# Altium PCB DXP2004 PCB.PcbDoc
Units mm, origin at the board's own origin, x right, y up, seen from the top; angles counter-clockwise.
Board outline 152.4 x 101.6 mm, 2 copper layers (Top Layer, Bottom Layer); 37 components, 0 nets, 178 pads, 0 vias.
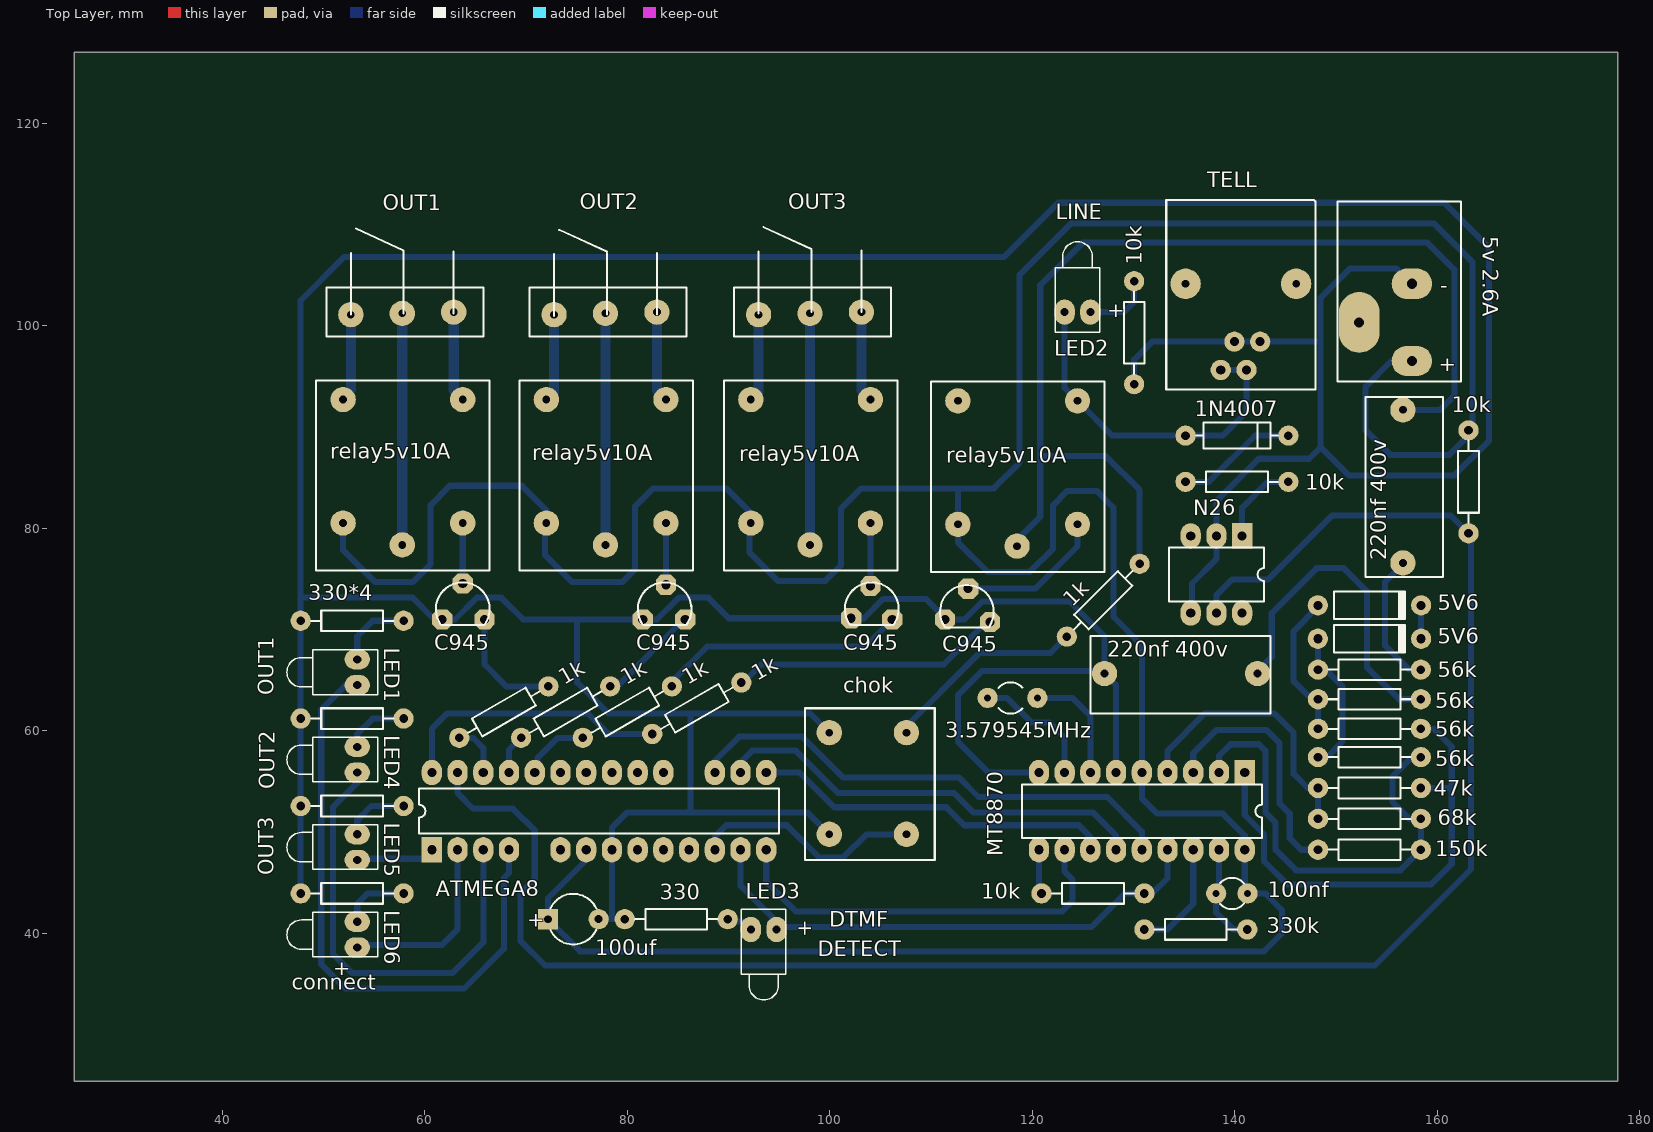
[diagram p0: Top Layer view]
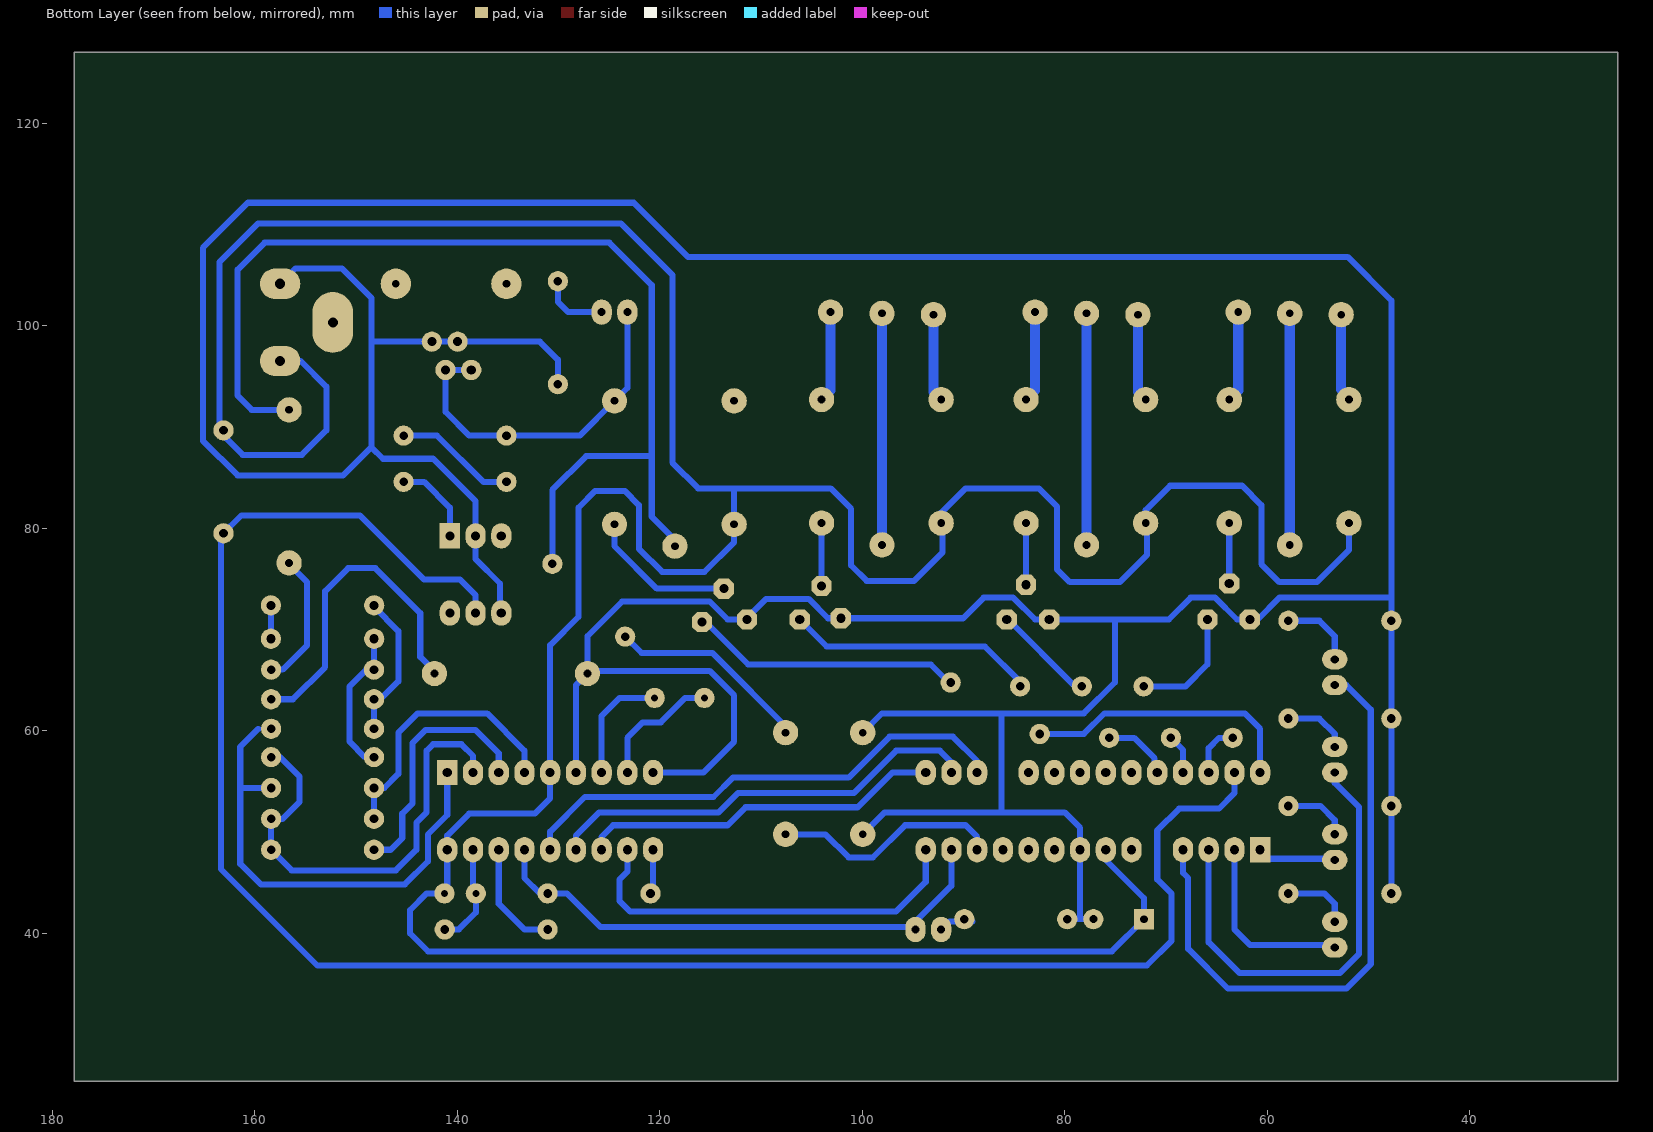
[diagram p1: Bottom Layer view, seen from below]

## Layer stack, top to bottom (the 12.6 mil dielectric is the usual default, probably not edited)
Top Layer: signal copper 0.0356
Dielectric: dielectric 0.32, FR-4, Dk 4.8
Bottom Layer: signal copper 0.0356

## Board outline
25.4,25.4 177.8,25.4 177.8,127 25.4,127

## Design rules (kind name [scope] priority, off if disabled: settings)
Clearance [All] p1: gap=0.254
ComponentClearance [All] p1: gap=0.254 collisioncheckmode=0
PolygonConnect [All] p1: connectstyle=Relief reliefconductorwidth=0.254 reliefentries=4 polygonreliefangle="90 Angle"
RoutingLayers [All] p1: top layer=Horizontal bottom layer=Vertical
RoutingVias [All] p1: holewidth=0.711 width=1.27 viastyle="Through Hole" minholewidth=0.711 minwidth=1.27 maxholewidth=0.711 maxwidth=1.27
SolderMaskExpansion [All] p1: expansion=0.102
TestPointUsage [All] p1: valid=0 allowmultiple=FALSE
Testpoint [All] p1: side=15 testpointundercomponent=TRUE minsize=1.016 maxsize=2.54 preferedsize=1.524 minholesize=0 maxholesize=1.016 preferedholesize=0.813 testpointgrid=0.025 style=1023 order=1234567890
Width [All] p1: maxlimit=0.254 minlimit=0.254 preferedwidth=0.254
16 further rules are at their usual default settings.

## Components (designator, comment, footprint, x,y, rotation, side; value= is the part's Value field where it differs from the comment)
1k "Comment" AXIAL-0.4 127,72.898 r45 top
1k "Comment" AXIAL-0.4 67.818,61.849 r30 top
1k "Comment" AXIAL-0.4 73.914,61.849 r30 top
1k "Comment" AXIAL-0.4 80.01,61.849 r30 top
1k "Comment" AXIAL-0.4 86.868,62.23 r30 top
1N4007 "Comment" DIODE-0.4 140.208,89.154 r0 top
3.579545MHz "Comment" BCY-W2/D3.1#1 117.856,63.246 r270 top
5V6 "Comment" DIO10.2-7X2.7 153.289,72.39 r0 top
5V6 "Comment" DIO10.2-7X2.7 153.289,69.088 r0 top
10k "Comment" AXIAL-0.4 163.068,84.582 r270 top
10k "Comment" AXIAL-0.4 125.984,43.942 r180 top
10k "Comment" AXIAL-0.4 130.048,99.314 r270 top
10k "Comment" AXIAL-0.4 140.208,84.582 r180 top
47k "Comment" AXIAL-0.4 153.289,54.356 r180 top
56k "Comment" AXIAL-0.4 153.289,57.404 r180 top
56k "Comment" AXIAL-0.4 153.289,60.198 r180 top
56k "Comment" AXIAL-0.4 153.289,63.119 r180 top
56k "Comment" AXIAL-0.4 153.289,66.04 r180 top
68k "Comment" AXIAL-0.4 153.289,51.308 r180 top
100nf "Comment" BCY-W2/D3.1#2 139.7,43.942 r90 top
100uf "Comment" CAPPR5-5X5 74.676,41.402 r0 top
150k "Comment" AXIAL-0.4 153.289,48.26 r180 top
330 "Comment" AXIAL-0.4 84.836,41.402 r0 top
330*4 "Comment" AXIAL-0.4 52.832,70.866 r180 top
330k "Comment" AXIAL-0.4 136.144,40.386 r180 top
ATMEGA8 "Comment" 28P3 77.216,52.07 r0 top
LED1 "Comment" LED-1 53.34,65.786 r180 top
LED2 "Comment" LED-1 124.46,101.346 r90 top
LED3 "Comment" LED-1 93.472,40.386 r270 top
LED4 "Comment" LED-1 53.34,57.15 r180 top
LED5 "Comment" LED-1 53.34,48.514 r180 top
LED6 "Comment" LED-1 53.34,39.878 r180 top
MT8870 "Comment" DIP-18 130.81,52.07 r180 top
N26 "Comment" DIP-6 138.176,75.438 r180 top
? "Comment" AXIAL-0.4 52.832,43.942 r180 top
? "Comment" AXIAL-0.4 52.832,52.578 r180 top
? "Comment" AXIAL-0.4 52.832,61.214 r180 top

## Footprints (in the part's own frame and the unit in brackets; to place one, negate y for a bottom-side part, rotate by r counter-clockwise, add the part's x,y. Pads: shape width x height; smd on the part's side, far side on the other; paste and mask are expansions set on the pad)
28P3 [mm] "DIP; 28 Leads; Row Spacing 7.62 mm; Pitch 2.54 mm"
  rect 2x2.5 hole 0.9: 1(-16.51,-3.81)
  oval 2x2.5 hole 0.9: 2(-13.97,-3.81) 3(-11.43,-3.81) 4(-8.89,-3.81) 6(-3.81,-3.81) 7(-1.27,-3.81) 8(1.27,-3.81) 9(3.81,-3.81) 10(6.35,-3.81) 11(8.89,-3.81) 12(11.43,-3.81) 13(13.97,-3.81) 14(16.51,-3.81) 15(16.51,3.81) 16(13.97,3.81) 17(11.43,3.81) 19(6.35,3.81) 20(3.81,3.81) 21(1.27,3.81) 22(-1.27,3.81) 23(-3.81,3.81) 24(-6.35,3.81) 25(-8.89,3.81) 26(-11.43,3.81) 27(-13.97,3.81) 28(-16.51,3.81)
  round 0 all layers, no hole: 5(-6.35,-3.81) 18(8.89,3.81)
  silkscreen extent -17.78,-2.23 17.78,2.23
AXIAL-0.4 [mm]
  round 2 hole 0.85: 1(-5.08,0) 2(5.08,0)
  silkscreen extent -4.06,-1.02 4.06,1.02
BCY-W2/D3.1#1 [mm]
  round 2 hole 0.7: 1(0,2.636) 2(0,-2.272)
  silkscreen extent -1.55,-1.19 1.55,1.17
BCY-W2/D3.1#2 [mm]
  round 2 hole 0.7: 1(0,1.55) 2(0,-1.55)
  silkscreen extent -1.55,-1.19 1.55,1.17
CAPPR5-5X5 [mm]
  rect 2x2 hole 0.75: 1(-2.5,0)
  round 2 hole 0.8: 2(2.5,0)
  silkscreen extent -2.26,-2.5 2.27,2.5
DIO10.2-7X2.7 [mm]
  round 2 hole 0.9: 1(-5.1,0) 2(5.1,0)
  silkscreen extent -3.5,-1.35 3.6,1.35
DIODE-0.4 [mm]
  round 2 hole 0.85: 1(-5.08,0) 2(5.08,0)
  silkscreen extent -4.06,-1.27 4.06,1.27
DIP-6 [mm]
  rect 2x2.5 hole 0.9: 1(-2.54,-3.81)
  oval 2x2.5 hole 0.9: 2(0,-3.81) 3(2.54,-3.81) 4(2.54,3.81) 5(0,3.81) 6(-2.54,3.81)
  silkscreen extent -4.7,-2.65 4.7,2.65
DIP-18 [mm]
  rect 2x2.5 hole 0.9: 1(-10.16,-3.81)
  oval 2x2.5 hole 0.9: 2(-7.62,-3.81) 3(-5.08,-3.81) 4(-2.54,-3.81) 5(0,-3.81) 6(2.54,-3.81) 7(5.08,-3.81) 8(7.62,-3.81) 9(10.16,-3.81) 10(10.16,3.81) 11(7.62,3.81) 12(5.08,3.81) 13(2.54,3.81) 14(0,3.81) 15(-2.54,3.81) 16(-5.08,3.81) 17(-7.62,3.81) 18(-10.16,3.81)
  silkscreen extent -11.85,-2.65 11.85,2.65
LED-1 [mm]
  oval 2.5x2 hole 0.8: 1(0,1.27) 2(0,-1.27)
  silkscreen extent -2,-2.2 6.95,2.2

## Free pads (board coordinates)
  round 2.5 hole 0.762: 0(51.943,80.518) 0(51.943,92.71) 0(52.705,101.092) 0(57.785,78.359) 0(57.785,101.219) 0(62.865,101.346) 0(72.009,80.518) 0(72.009,92.71) 0(72.771,101.092) 0(77.851,78.359) 0(77.851,101.219) 0(82.931,101.346) 0(92.202,80.518) 0(92.202,92.71) 0(92.964,101.092) 0(98.044,78.359) 0(98.044,101.219) 0(103.124,101.346) 0(112.649,80.391) 0(112.649,92.583) 0(118.491,78.232) 1(63.754,80.518) 1(63.754,92.71) 1(83.82,80.518) 1(83.82,92.71) 1(104.013,80.518) 1(104.013,92.71) 1(124.46,80.391) 1(124.46,92.583) 4(99.949,49.784) 4(99.949,59.817) 5(107.569,49.784) 5(107.569,59.817) 6(127.127,65.659) 6(156.591,76.581) 7(142.24,65.659) 7(156.591,91.694)
  oval 4x3 hole 1: 0(157.48,96.52) 1(157.48,104.14)
  oct 2x2 hole 0.9: 1(61.722,70.993) 1(81.534,70.993) 1(102.108,71.12) 1(111.379,70.993) 2(63.754,74.549) 2(83.82,74.422) 2(104.013,74.295) 2(113.665,74.041) 3(65.913,70.993) 3(85.725,70.993) 3(106.172,70.993) 3(115.824,70.739)
  round 2 hole 0.9: 1(138.606,95.631) 1(139.954,98.428) 2(141.146,95.631) 2(142.494,98.428)
  round 3 hole 0.762: 2(135.13,104.14) 3(146.05,104.14)
  oval 4x6 hole 1: 2(152.273,100.33)

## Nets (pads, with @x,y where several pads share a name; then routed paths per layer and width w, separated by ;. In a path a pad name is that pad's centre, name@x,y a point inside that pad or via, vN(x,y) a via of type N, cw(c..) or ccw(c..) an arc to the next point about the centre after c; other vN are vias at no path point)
pads on no net: 1k.1 1k.2 1N4007.1 1N4007.2 3.579545MHz.1 3.579545MHz.2 5V6.1 5V6.2 10k.1 10k.2 47k.1 47k.2 56k.1 56k.2 68k.1 68k.2 100nf.1 100nf.2 100uf.1 100uf.2 150k.1 150k.2 330*4.1 330*4.2 330.1 330.2 330k.1 330k.2 ?.1 ?.2 ATMEGA8.1 ATMEGA8.2 ATMEGA8.3 ATMEGA8.4 ATMEGA8.5 ATMEGA8.6 ATMEGA8.7 ATMEGA8.8 ATMEGA8.9 ATMEGA8.10 ATMEGA8.11 ATMEGA8.12 ATMEGA8.13 ATMEGA8.14 ATMEGA8.15 ATMEGA8.16 ATMEGA8.17 ATMEGA8.18 ATMEGA8.19 ATMEGA8.20 ATMEGA8.21 ATMEGA8.22 ATMEGA8.23 ATMEGA8.24 ATMEGA8.25 ATMEGA8.26 ATMEGA8.27 ATMEGA8.28 LED1.1 LED1.2 LED2.1 LED2.2 LED3.1 LED3.2 LED4.1 LED4.2 LED5.1 LED5.2 LED6.1 LED6.2 MT8870.1 MT8870.2 MT8870.3 MT8870.4 MT8870.5 MT8870.6 MT8870.7 MT8870.8 MT8870.9 MT8870.10 MT8870.11 MT8870.12 MT8870.13 MT8870.14 MT8870.15 MT8870.16 MT8870.17 MT8870.18 N26.1 N26.2 N26.3 N26.4 N26.5 N26.6
copper on no net: | length 2220.7
  Top Layer w1: 156.591,97.409 158.115,97.409 158.877,96.647 ; 156.718,95.758 157.48,96.52 ; 157.226,104.14 157.48,104.14
  Bottom Layer w0.6: 47.752,44.069 47.752,79.248 ; 47.752,73.279 47.879,73.152 58.801,73.152 60.96,70.993 61.722,70.993 62.992,70.993 65.151,73.152 67.564,73.152 69.723,70.993 81.534,70.993 82.931,70.993 85.09,73.152 88.011,73.152 90.043,71.12 102.108,71.12 103.378,71.12 105.283,73.025 109.474,73.025 111.379,71.12 111.379,70.993 113.284,70.993 115.062,72.771 117.602,72.771 123.698,72.771 127.127,69.342 127.127,65.659 128.27,64.516 128.27,58.166 ; 47.752,78.486 47.752,102.489 52.07,106.807 117.221,106.807 122.555,112.141 160.655,112.141 165.1,107.696 165.1,88.646 161.671,85.217 151.257,85.217 148.463,88.011 ; 51.943,80.518 51.943,77.851 55.118,74.676 58.801,74.676 60.579,76.454 60.579,82.296 62.484,84.201 69.596,84.201 72.009,81.788 72.009,80.518 71.882,80.391 71.882,77.343 74.549,74.676 79.502,74.676 80.772,75.946 80.772,82.169 82.55,83.947 89.789,83.947 92.202,81.534 92.202,80.518 92.075,80.391 92.075,77.597 94.869,74.803 99.568,74.803 101.092,76.327 101.092,81.915 103.124,83.947 110.744,83.947 ; 53.213,38.862 61.722,38.862 63.246,40.386 63.246,48.26 ; 53.213,47.371 59.817,47.371 60.706,48.26 ; 53.34,41.148 53.34,42.926 54.356,43.942 57.912,43.942 ; 53.34,49.784 53.34,51.181 54.737,52.578 57.912,52.578 ; 53.34,55.88 53.34,54.864 50.927,52.451 50.927,37.973 52.832,36.068 62.738,36.068 65.786,39.116 65.786,48.26 ; 53.34,58.42 53.34,59.69 54.864,61.214 57.912,61.214 ; 53.34,64.516 52.197,64.516 49.784,62.103 49.784,36.957 52.197,34.544 63.881,34.544 67.818,38.481 67.818,45.466 68.326,45.974 68.326,48.26 ; 53.34,67.056 53.34,69.342 54.864,70.866 57.912,70.866 ; 60.706,55.88 60.706,60.198 62.23,61.722 76.073,61.722 78.105,59.69 82.469,59.69 ; 63.246,55.88 63.246,53.848 64.77,52.324 68.707,52.324 70.866,50.165 70.866,45.339 69.469,43.942 69.469,39.243 71.882,36.83 73.152,36.83 153.797,36.83 163.322,46.355 163.322,76.073 ; 63.419,59.309 64.77,59.309 65.786,58.293 65.786,55.88 ; 63.754,73.914 63.754,80.518 ; 65.913,70.993 65.913,66.548 68.072,64.389 72.217,64.389 ; 68.326,55.88 68.326,58.12 69.515,59.309 ; 71.12,55.88 71.12,57.277 73.152,59.309 75.611,59.309 ; 75.057,70.993 75.057,64.77 78.105,61.722 83.566,61.722 ; 75.946,48.26 75.946,47.244 72.176,43.474 72.176,41.402 75.351,38.227 82.931,38.227 ; 77.176,41.402 79.502,41.402 79.756,41.148 ; 78.486,41.402 78.486,46.228 ; 78.486,45.732 78.486,48.26 78.486,50.419 80.01,51.943 84.328,51.943 97.79,51.943 99.949,49.784 ; 78.486,64.516 79.121,64.516 85.598,70.993 85.725,70.993 ; 82.677,38.227 142.875,38.227 144.653,40.005 144.653,42.291 143.002,43.942 141.25,43.942 140.97,44.222 140.97,48.26 ; 83.185,61.722 91.821,61.722 98.044,61.722 99.949,59.817 ; 83.693,73.914 83.82,74.041 83.82,80.518 ; 84.409,64.389 84.409,64.851 87.884,68.326 103.505,68.326 106.172,70.993 ; 86.233,51.943 86.233,61.722 ; 88.646,48.26 88.646,49.53 89.789,50.673 95.758,50.673 98.933,47.498 101.346,47.498 103.632,49.784 107.569,49.784 ; 88.646,56.134 88.646,57.023 91.059,59.436 97.282,59.436 101.346,55.372 112.776,55.372 114.681,53.467 127.381,53.467 130.81,50.038 130.81,48.26 ; 89.102,41.189 91.399,41.189 92.202,40.386 ; 91.186,48.26 91.186,44.704 95.25,40.64 125.857,40.64 129.159,43.942 131.572,43.942 131.826,43.942 133.35,45.466 133.35,48.26 ; 91.186,55.88 91.186,56.896 92.329,58.039 96.647,58.039 100.838,53.848 112.268,53.848 114.173,51.943 125.984,51.943 128.27,49.657 128.27,48.26 ; 91.267,64.77 91.44,64.77 93.218,66.548 111.252,66.548 115.697,70.993 ; 93.726,48.26 93.726,45.085 96.647,42.164 122.936,42.164 123.952,43.18 123.952,45.339 123.19,46.101 123.19,48.26 ; 93.726,55.88 97.028,55.88 100.457,52.451 111.506,52.451 113.284,50.673 124.587,50.673 125.73,49.53 125.73,48.26 ; 104.013,80.518 104.013,74.041 104.14,73.914 ; 107.569,59.817 106.934,59.817 114.808,67.691 121.793,67.691 123.408,69.306 ; 110.109,83.947 116.205,83.947 118.745,86.487 118.745,105.029 123.825,110.109 159.639,110.109 163.449,106.299 163.449,89.535 161.163,87.249 155.321,87.249 152.908,89.662 152.908,93.98 155.448,96.52 157.48,96.52 ; 112.649,83.82 112.649,80.391 112.649,78.613 115.57,75.692 119.761,75.692 122.047,77.978 122.047,82.296 123.444,83.693 126.365,83.693 128.016,82.042 128.016,71.247 130.81,68.453 130.81,57.531 ; 113.538,74.041 120.269,74.041 124.46,78.232 124.46,80.391 ; 115.584,63.246 117.475,63.246 119.888,60.833 121.666,60.833 123.19,59.309 123.19,55.88 ; 118.618,78.232 118.491,78.232 118.491,78.867 120.777,81.153 120.777,104.013 124.968,108.204 159.004,108.204 161.671,105.537 161.671,93.091 160.274,91.694 156.591,91.694 ; 120.492,63.246 123.952,63.246 125.73,61.468 125.73,55.88 ; 120.65,48.26 120.65,44.704 121.412,43.942 ; 120.65,55.88 115.697,55.88 112.649,58.928 112.649,63.5 115.062,65.913 127,65.913 127.127,66.04 ; 120.777,87.122 127.254,87.122 130.592,83.784 130.592,76.49 ; 123.19,100.076 123.19,101.346 123.19,93.853 124.46,92.583 127.889,89.154 135.128,89.154 138.811,89.154 141.146,91.489 141.146,95.631 138.606,95.631 138.557,95.631 ; 125.73,101.346 129.032,101.346 130.048,102.362 130.048,104.394 ; 128.27,55.88 128.27,58.801 ; 130.048,94.234 130.048,96.647 131.829,98.428 139.954,98.428 142.494,98.428 148.463,98.425 ; 130.81,55.626 130.81,58.166 ; 130.81,55.88 130.81,53.34 132.334,51.816 138.811,51.816 140.97,49.657 140.97,48.26 ; 131.064,40.386 133.35,40.386 135.89,42.926 135.89,48.26 ; 133.35,55.88 133.35,58.039 137.033,61.722 143.891,61.722 145.796,59.817 145.796,55.753 147.193,54.356 148.209,54.356 148.209,51.054 ; 135.128,84.582 137.414,84.582 141.986,89.154 145.288,89.154 ; 135.763,71.882 135.763,74.549 138.176,76.962 138.176,79.248 138.176,82.677 142.367,86.868 147.32,86.868 148.463,88.011 ; 135.89,55.88 135.89,57.785 138.176,60.071 143.129,60.071 144.399,58.801 144.399,52.832 145.415,51.816 145.415,49.403 146.558,48.26 148.209,48.26 ; 138.176,71.628 138.176,73.406 139.7,74.93 143.256,74.93 149.606,81.28 161.29,81.28 163.322,79.248 163.322,75.819 ; 138.43,48.26 138.43,44.222 138.15,43.942 138.15,42.063 139.827,40.386 141.224,40.386 ; 138.43,55.88 138.43,57.531 139.573,58.674 142.367,58.674 143.002,58.039 143.002,51.943 144.018,50.927 144.018,48.26 146.05,46.228 156.337,46.228 158.369,48.26 158.369,51.308 157.226,51.308 155.575,52.959 155.575,55.499 157.48,57.404 158.369,57.404 ; 140.716,79.248 140.716,82.042 143.256,84.582 145.288,84.582 ; 140.97,45.212 140.97,48.26 ; 140.97,55.88 140.97,51.689 142.875,49.784 142.875,47.117 145.161,44.831 159.385,44.831 161.417,46.863 161.417,58.42 159.639,60.198 ; 142.24,65.659 142.24,65.913 143.637,67.31 143.637,71.628 148.082,76.073 150.749,76.073 153.035,73.787 153.035,66.294 156.21,63.119 158.369,63.119 ; 148.189,69.088 148.189,66.06 148.209,66.04 148.971,66.04 150.622,64.389 150.622,58.928 149.098,57.404 148.209,57.404 ; 148.189,72.39 148.189,72.243 145.796,69.85 145.796,64.897 147.574,63.119 148.209,63.119 148.209,60.198 ; 156.591,76.581 156.591,76.454 154.813,74.676 154.813,68.453 157.226,66.04 158.369,66.04 ; 157.48,104.14 155.956,105.664 151.384,105.664 148.463,102.743 148.463,88.011 ; 158.369,54.356 161.29,54.356 ; 158.389,69.088 158.389,72.39
  Bottom Layer w1: 51.689,92.71 52.705,93.726 52.705,101.092 ; 57.785,78.359 57.785,101.219 ; 62.865,101.346 62.865,93.599 63.754,92.71 ; 72.009,92.71 72.771,93.472 72.771,101.092 ; 77.851,78.359 77.851,101.219 ; 82.931,101.346 82.931,93.599 83.82,92.71 ; 92.202,92.71 92.964,93.472 92.964,101.092 ; 98.044,101.219 98.044,78.613 98.171,78.486 ; 103.124,101.346 103.124,93.599 104.013,92.71 ; 118.491,78.486 118.618,78.359

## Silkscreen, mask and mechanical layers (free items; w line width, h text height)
Top Overlay:
  lines w0.2: 52.705,101.092 52.705,107.188 ; 53.213,109.601 57.912,107.442 ; 57.912,101.219 57.912,107.315 ; 61.583,70.489 cw(c63.754,72.009) 65.925,70.489 ; 61.654,70.459 65.854,70.459 ; 62.865,101.219 62.865,107.315 ; 72.771,100.965 72.771,107.061 ; 73.279,109.474 77.978,107.315 ; 77.978,101.092 77.978,107.188 ; 81.522,70.489 cw(c83.693,72.009) 85.864,70.489 ; 81.593,70.459 85.793,70.459 ; 82.931,101.092 82.931,107.188 ; 92.964,101.219 92.964,107.315 ; 93.472,109.728 98.171,107.569 ; 98.171,101.346 98.171,107.442 ; 101.969,70.489 cw(c104.14,72.009) 106.311,70.489 ; 102.04,70.459 106.24,70.459 ; 103.124,101.346 103.124,107.442 ; 111.367,70.235 cw(c113.538,71.755) 115.709,70.235 ; 111.438,70.205 115.638,70.205 ; 133.223,112.395 133.223,93.726 147.955,93.726 147.955,112.266 147.957,112.268 147.83,112.395 133.225,112.395 ; 49.276,75.819 49.276,94.615 49.657,94.615 66.421,94.615 66.421,75.819 49.276,75.819 ; 50.292,98.933 50.292,103.759 65.786,103.759 65.786,98.933 50.292,98.933 ; 69.342,75.819 69.342,94.615 69.723,94.615 86.487,94.615 86.487,75.819 69.342,75.819 ; 70.358,98.933 70.358,103.759 85.852,103.759 85.852,98.933 70.358,98.933 ; 89.535,75.819 89.535,94.615 89.916,94.615 106.68,94.615 106.68,75.819 89.535,75.819 ; 90.551,98.933 90.551,103.759 106.045,103.759 106.045,98.933 90.551,98.933 ; 97.536,47.244 97.536,62.23 110.363,62.23 110.363,47.244 97.536,47.244 ; 109.982,75.692 109.982,94.488 110.363,94.488 127.127,94.488 127.127,75.692 109.982,75.692 ; 125.73,61.722 143.51,61.722 143.51,69.342 125.73,69.342 125.73,61.722 ; 150.114,94.488 162.306,94.488 162.306,97.028 162.306,112.268 150.114,112.268 150.114,94.488 ; 152.908,75.184 152.908,92.964 160.528,92.964 160.528,75.184 152.908,75.184
  text "TELL" at 137.287,113.665 h1.52
  text "OUT2" at 75.311,111.506 h1.52
  text "OUT3" at 95.885,111.506 h1.52
  text "OUT1" at 55.88,111.379 h1.52
  text "LINE" at 122.301,110.49 h1.52
  text "5v 2.6A" at 164.465,108.839 h1.52 r270
  text "-" at 160.274,103.251 h1.52
  text "+" at 127.381,100.838 h1.52
  text "+" at 160.147,95.504 h1.52
  text "relay5v10A" at 50.673,86.868 h1.52
  text "relay5v10A" at 70.612,86.741 h1.52
  text "relay5v10A" at 91.059,86.614 h1.52
  text "relay5v10A" at 111.506,86.487 h1.52
  text "220nf 400v" at 154.94,76.835 h1.52 r90
  text "C945" at 60.96,67.945 h1.52
  text "C945" at 80.899,67.945 h1.52
  text "C945" at 101.346,67.945 h1.52
  text "C945" at 111.125,67.818 h1.52
  text "220nf 400v" at 127.381,67.31 h1.52
  text "chok" at 101.346,63.754 h1.52
  text "OUT1" at 45.085,63.5 h1.52 r90
  text "OUT2" at 45.212,54.229 h1.52 r90
  text "OUT3" at 45.085,45.72 h1.52 r90
  text "DTMF" at 99.949,40.64 h1.52
  text "+" at 98.171,39.624 h1.52 r90
  text "DETECT" at 98.806,37.719 h1.52
  text "+" at 52.705,37.084 h1.52 r180
  text "connect" at 46.863,34.417 h1.52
